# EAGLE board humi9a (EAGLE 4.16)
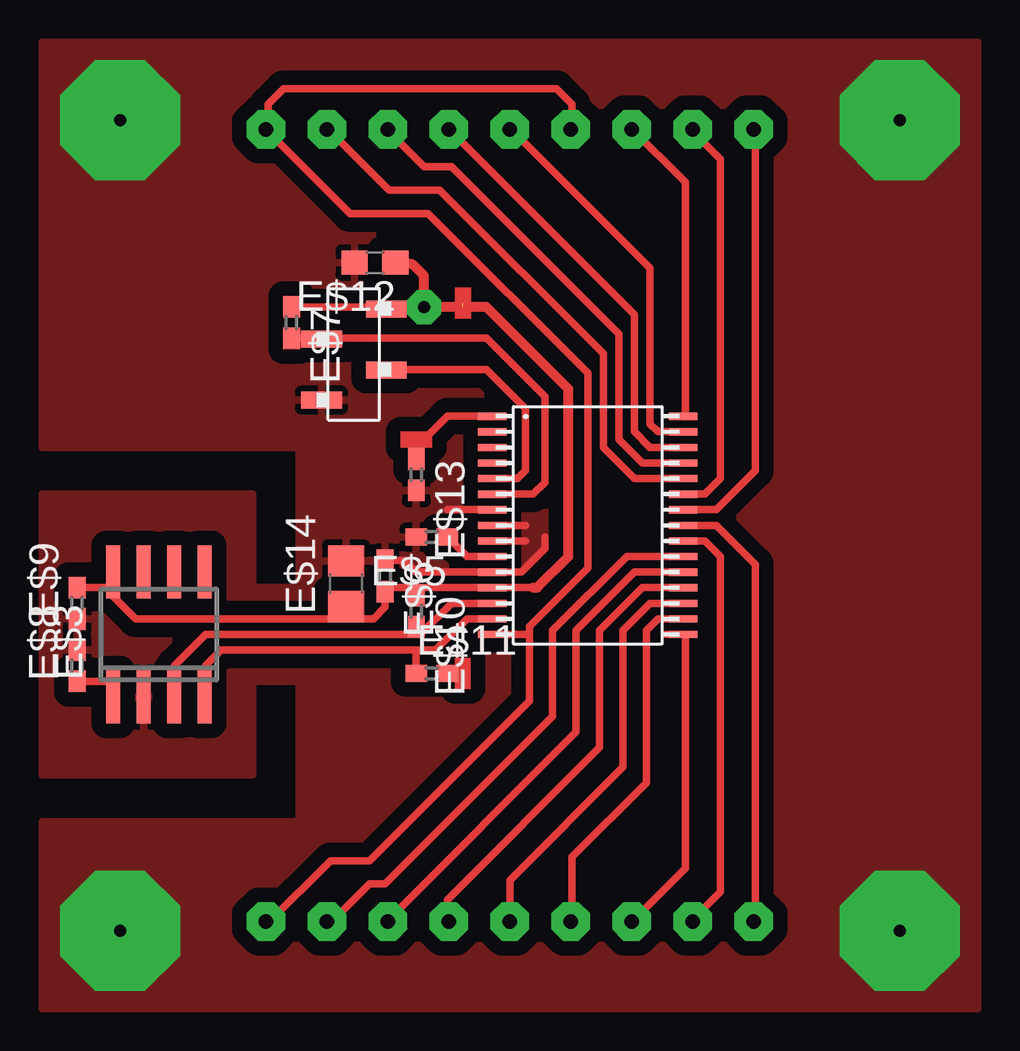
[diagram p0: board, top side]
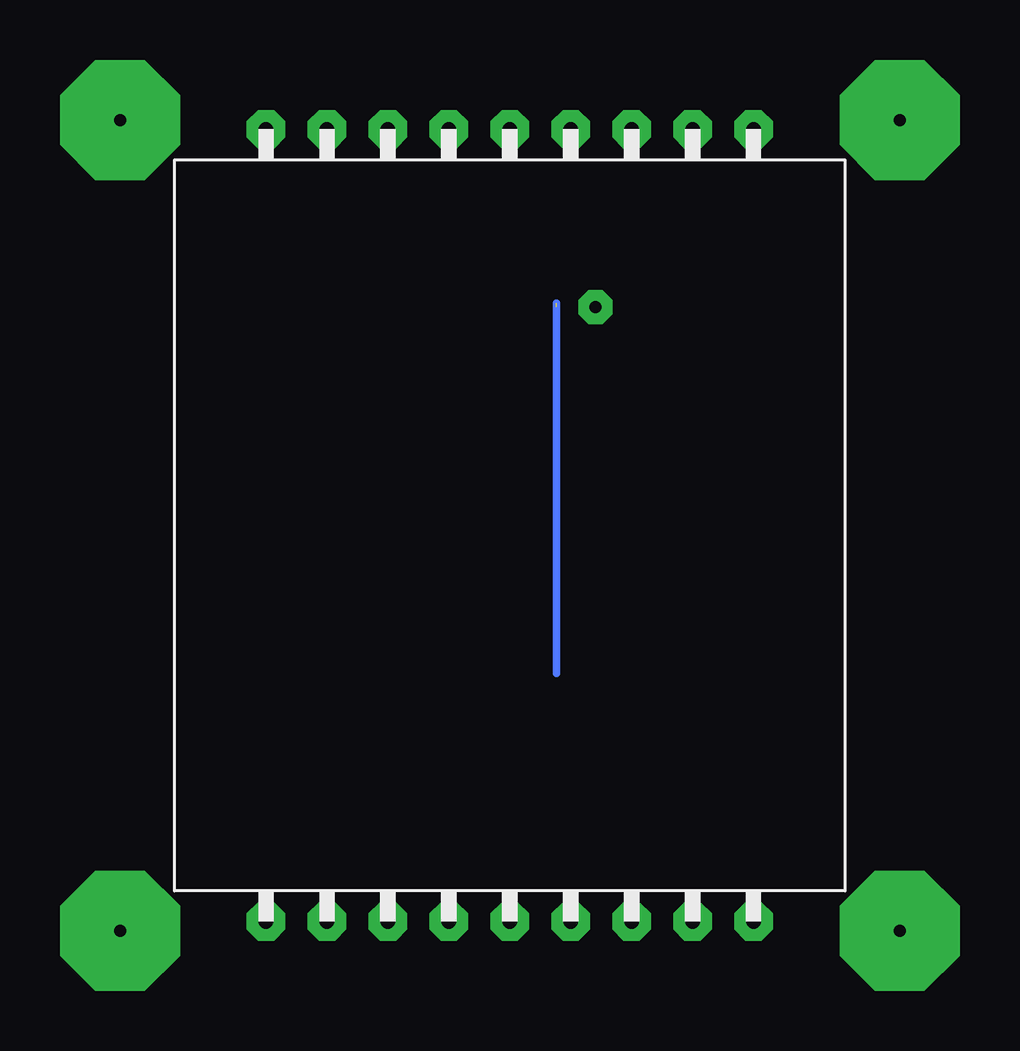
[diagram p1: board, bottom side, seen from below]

No outline drawn. Coordinates in mm, seen from the top.
Copper layers (1*16): Top 0.035mm / dielectric 1.5mm / Bottom 0.035mm
Design rules "default": minimum track width 10mil, minimum drill 24mil, track to track 8mil, track to pad 8mil, pad to pad 8mil, via to via 8mil, smd to smd 8mil, copper to edge 40mil, drill to drill 8mil, minimum pad ring 10mil, minimum via ring 8mil, stop-mask expansion 4mil, vias tented up to drill 0mil, thermal gap 10mil

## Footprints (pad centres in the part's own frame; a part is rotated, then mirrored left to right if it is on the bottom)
VI201 = drill 0.6 pad 1.6 octagon: 1 -10.16,-16.51; 2 -7.62,-16.51; 3 -5.08,-16.51; 4 -2.54,-16.51; 5 0,-16.51; 6 2.54,-16.51; 7 5.08,-16.51; 8 7.62,-16.51; 9 10.16,-16.51; 10 10.16,16.51; 11 7.62,16.51; 12 5.08,16.51; 13 2.54,16.51; 14 0,16.51; 15 -2.54,16.51; 16 -5.08,16.51; 17 -7.62,16.51; 18 -10.16,16.51
TSSOP30-RL78 = smd 0.3 x 1.2: 1 -4.55,-3.981; 2 -3.9,-3.981; 3 -3.25,-3.981; 4 -2.6,-3.981; 5 -1.95,-3.981; 6 -1.3,-3.981; 7 -0.65,-3.981; 8 0,-3.981; 9 0.65,-3.981; 10 1.3,-3.981; 11 1.95,-3.981; 12 2.6,-3.981; 13 3.25,-3.981; 14 3.9,-3.981; 15 4.55,-3.981; 16 4.55,3.981; 17 3.9,3.981; 18 3.25,3.981; 19 2.6,3.981; 20 1.95,3.981; 21 1.3,3.981; 22 0.65,3.981; 23 0,3.981; 24 -0.65,3.981; 25 -1.3,3.981; 26 -1.95,3.981; 27 -2.6,3.981; 28 -3.25,3.981; 29 -3.9,3.981; 30 -4.55,3.981
SO08 = smd 0.6 x 2.2: 1 -1.905,-2.6; 2 -0.635,-2.6; 3 0.635,-2.6; 4 1.905,-2.6; 5 1.905,2.6; 6 0.635,2.6; 7 -0.635,2.6; 8 -1.905,2.6
HEADERS4 = smd 0.7 x 1.7: P$1 1.27,1.35; P$3 -1.28,1.35; P$4 -0.03,-1.35; P$5 2.52,-1.35
C0402 = smd 0.9 x 0.7: 1 -0.65,0; 2 0.65,0
C0603 = smd 1.1 x 1: 1 -0.85,0; 2 0.85,0
C0805 = smd 1.3 x 1.5: 1 -0.95,0; 2 0.95,0

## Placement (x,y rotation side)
E$1  [VI201]  19.5,20.15 180 bottom
E$2  [TSSOP30-RL78]  22.75,20.15 270 top
E$3  [SO08]  4.88,15.6 0 top
E$4  [HEADERS4]  13,26.65 90 top
E$5  [C0402]  16.25,19.66 180 top
E$6  [C0402]  14.3,18.04 270 top
E$7  [C0402]  10.4,28.6 270 top
E$8  [C0402]  1.46,14.3 90 top
E$9  [C0402]  1.46,16.9 90 top
E$10  [C0402]  15.6,16.57 270 top
E$11  [C0402]  16.25,13.97 0 top
E$12  [C0603]  13.88,31.1 180 top
E$13  [C0402]  15.6,22.26 270 top
E$14  [C0805]  12.68,17.71 90 top

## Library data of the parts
E$1 = display-lcd
E$2 E$4 = sb
E$3 E$5-E$14 = ref-packages

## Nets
GND: E$3.2 E$4.P$3 E$5.2 E$6.1 E$8.2 E$9.1 E$12.2 E$13.2 E$14.2
PWR: E$6.2 E$7.1 E$9.2
S$18: E$5.1
S$26: E$8.1

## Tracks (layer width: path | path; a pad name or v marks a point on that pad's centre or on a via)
COM
  Top 0.305: 22.1,36.56 22.1,37.7 21.45,38.35 10.07,38.35 9.43,37.7 9.43,36.56 12.84,33.15 16.09,33.15 22.75,26.49 22.75,18.36 20.31,15.93 20.31,15.6 | 9.43,3.58 12.03,6.17 13.65,6.17 20.31,12.84 20.31,15.6 | 20.31,15.6 18.85,15.6
GND  (via drill 0.5 pad 5)
  Top 0.305: 20.96,19.66 20.96,19.18 19.99,18.2 15.6,18.2 15.11,18.69 E$6.1 | 18.85,20.15 20.15,20.15 | 18.85,19.5 20.15,19.5 | 16.9,20.8 19.18,20.8
  other vias: 3.25,3.25 35.75,3.25 3.25,37.05 35.75,37.05
  pour Top (isolate 0.61): 0,0 0,7.8 10.72,7.8 10.72,13.65 8.78,13.65 8.78,9.75 0,9.75 0,21.45 8.78,21.45 8.78,17.55 10.72,17.55 10.72,23.4 0,23.4 0,40.3 39,40.3 39,0
PWR  (1 unrouted)
  Top 0.305: 2.92,17.23 3.9,16.25 13.81,16.25 14.3,16.74 E$6.2 14.3,17.55 20.48,17.55 | 2.92,17.23 2.92,18.85 | 15.93,29.25 E$7.1 | E$9.2 2.92,17.55 2.92,17.23
  Top 0.406: 20.48,17.55 20.64,17.55 21.94,18.85 21.94,25.84 18.52,29.25 17.55,29.25 15.93,29.25 15.93,30.55 15.44,31.04 14.95,31.04
  Bottom 0.305: 17.55,13.97 17.55,29.41
S$1  (via drill 0.5 pad 1.42)
  other vias: 15.93,29.25
S$2
  Top 0.305: 11.86,3.74 11.86,3.58 12.03,3.58 13.65,5.2 14.3,5.2 21.29,12.19 21.29,15.76 24.38,18.85 26.65,18.85
S$4
  Top 0.305: 24.54,36.73 26.81,34.45 26.81,24.7
S$5
  Top 0.305: 26.65,24.05 25.68,24.05 25.35,24.38 25.35,30.88 19.66,36.56
S$6
  Top 0.305: 26.65,23.4 25.35,23.4 24.7,24.05 24.7,28.93 17.06,36.56
S$7
  Top 0.305: 26.65,22.75 25.02,22.75 24.05,23.73 24.05,28.11 17.06,35.1 15.93,35.1 14.3,36.73
S$8
  Top 0.305: 26.65,22.1 24.7,22.1 23.4,23.4 23.4,27.3 16.57,34.12 14.46,34.12 11.86,36.73
S$9
  Top 0.305: 27.3,21.45 27.62,21.45 28.27,22.1 28.27,35.42 27.14,36.56
S$10
  Top 0.305: 26.65,20.8 28.11,20.8 29.74,22.43 29.74,36.56
S$11
  Top 0.305: 26.65,20.15 28.11,20.15 29.74,18.52 29.74,3.74
S$12
  Top 0.305: 26.65,19.5 27.62,19.5 28.27,18.85 28.27,4.88 27.14,3.74
S$13
  Top 0.305: 14.46,3.74 22.26,11.54 22.26,15.76 24.7,18.2 26.65,18.2
S$14
  Top 0.305: 16.9,3.9 16.9,4.55 23.24,10.89 23.24,15.76 25.02,17.55 26.65,17.55
S$15
  Top 0.305: 19.5,3.9 19.5,5.36 24.21,10.07 24.21,15.76 25.35,16.9 26.65,16.9
S$16
  Top 0.305: 22.1,3.9 22.1,6.34 25.19,9.43 25.19,15.76 25.68,16.25 26.65,16.25
S$17
  Top 0.305: 24.7,3.74 26.81,5.85 26.81,15.6 26,15.6
S$18
  Top 0.305: E$5.1 17.71,18.85 18.85,18.85
S$19
  Top 0.305: 15.6,23.24 15.6,23.4 16.9,24.7 18.85,24.7
S$21
  Top 0.305: 18.85,22.1 19.82,22.1 20.15,22.43 20.15,25.02 18.52,26.65 14.3,26.65
S$22
  Top 0.305: 18.85,21.45 20.48,21.45 20.96,21.94 20.96,25.51 18.52,27.95 10.4,27.95
S$26
  Top 0.305: E$8.1 2.92,13.65
SCL
  Top 0.305: 5.53,13.65 5.53,14.3 6.83,15.6 15.76,15.6 17.06,16.9 18.85,16.9
SDA
  Top 0.305: 6.83,13.65 6.83,14.3 7.47,14.95 15.6,14.95 | 18.85,16.25 17.71,16.25 16.41,14.95 15.6,14.95 | 15.6,14.95 15.6,13.97
(copper drawn outside any net)
  shapes: Top area x3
